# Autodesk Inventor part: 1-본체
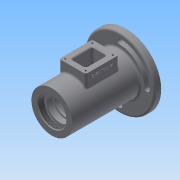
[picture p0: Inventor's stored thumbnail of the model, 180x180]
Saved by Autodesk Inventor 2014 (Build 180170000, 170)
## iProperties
Created: 2017-05
Part Number: 1-본체
Material: Generic
Document SubType Name: Modeling
Designer: user
Density: 1 g/cm^3
Appearance: Default
Author: user
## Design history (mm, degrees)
sketch "Sketch1"
  geometry: L1 (0, 0)-(115, 0); L2 (0, 0)-(0, 31); L3 (0, 31)-(102, 31); L4 (102, 31)-(102, 53); L5 (102, 53)-(112, 53); L6 (112, 53)-(112, 31); L7 (112, 31)-(115, 31); L8 (115, 31)-(115, 0)
  constraints: 16 end point, 4 parallel, 2 perpendicular, 1 collinear, 1 horizontal
  dimensions: "d0" = 62 diameter of L3 L1; "d1" = 106 diameter of L5 L1; "d2" = 62 diameter of L7 L1; "d3" = 10 distance of L4.end L5.end; "d4" = 3 distance from line of L5.end L8; "d5" = 115 distance between parallel lines of L2 L8
revolve "Revolution1" sketch "Sketch1" stored, may be unused: angle "d6" = 90 deg
sketch "Sketch4"
  geometry: L1 (0, 0)-(115, 0); L2 (115, -31)-(115, 31) reference; L3 (0, 0)-(0, 21); L4 (0, 21)-(9, 21); L5 (0, -31)-(0, 31) reference; L6 (9, 21)-(9, 24); L7 (0, 31)-(102, 31) reference; L8 (9, 24)-(12, 24); L9 (12, 24)-(12, 20); L10 (12, 20)-(21, 20); L11 (21, 20)-(21, 17.5); L12 (21, 17.5)-(24.25, 17.5); L13 (24.25, 17.5)-(24.25, 18.5); L14 (24.25, 18.5)-(26, 18.5); L15 (26, 18.5)-(26, 17.5); L16 (26, 17.5)-(37, 17.5); L17 (37, 17.5)-(37, 26); L18 (37, 26)-(75, 26); L19 (75, 26)-(75, 17.5); L20 (75, 17.5)-(86, 17.5); L21 (86, 17.5)-(86, 16.5); L22 (86, 16.5)-(91, 16.5); L23 (91, 16.5)-(91, 10); L24 (91, 10)-(93.7, 10); L25 (93.7, 10)-(93.7, 12.5); L26 (93.7, 12.5)-(101, 12.5); L27 (101, 12.5)-(101, 16); L28 (101, 16)-(115, 22); L29 (115, 0)-(115, 22)
  constraints: 52 end point, 12 parallel, 11 perpendicular, 1 collinear, 1 midpoint, 1 point on line, 1 vertical
  dimensions: "d10" = 42 diameter of L4 L1; "d11" = 48 diameter of L8 L1; "d12" = 40 diameter of L10 L1; "d13" = 3 distance of L6.end L8.end; "d14" = 12 distance between parallel lines of L9 L5; "d15" = 21 distance between parallel lines of L5 L11; "d16" = 1.75 distance of L13.end L14.end; "d17" = 37 diameter of L14 L1; "d18" = 35 diameter of L12 L1; "d19" = 26 distance from line of L5 L14.end; "d20" = 11 distance of L15.end L16.end; "d21" = 35 diameter of L16 L1; "d22" = 52 diameter of L18 L1; "d29" = 38 distance of L17.end L18.end; "d33" = 35 diameter of L20 L1; "d34" = 11 distance of L19.end L20.end; "d35" = 32 diameter of L27.end L1; "d36" = 44 diameter of L28.end L1; "d37" = 14 distance from line of L2 L27.end; "d38" = 25 diameter of L26 L1; "d39" = 20 diameter of L24 L1; "d40" = 7.3 distance between parallel lines of L25 L27; "d41" = 2.7 distance of L23.end L24.end; "d42" = 33 diameter of L22 L1
revolve "Revolution2" sketch "Sketch4" stored, may be unused: angle "d43" = 90 deg
workplane "Work Plane2"
sketch "Sketch5"
  geometry: L1 (-81, 20)-(-31, 20); L2 (-31, 20)-(-31, -20); L3 (-31, -20)-(-81, -20); L4 (-81, -20)-(-81, 20); L5 (0, 31)-(0, -31) reference; 1 further point
  constraints: 8 end point, 2 parallel, 1 horizontal, 1 perpendicular
  dimensions: "d46" = 50 distance of L1.start L1.end; "d47" = 20 vertical distance of point (0, 0) L1.end; "d48" = 40 distance of L1.end L2.end; "d49" = 31 distance between parallel lines of L5 L2
extrude "Extrusion1" join sketch "Sketch5" stored distance "d50" = 10; taper "d51" = 0 deg
sketch "Sketch6"
  geometry: L1 (-72, 11)-(-40, 11); L2 (-40, 11)-(-40, -11); L3 (-40, -11)-(-72, -11); L4 (-72, -11)-(-72, 11); L5 (0, 31)-(0, -31) reference; 1 further point
  constraints: 8 end point, 2 parallel, 1 horizontal, 1 perpendicular
  dimensions: "d52" = 22 distance of L1.end L2.end; "d53" = 11 distance from line of point (0, 0) L1; "d54" = 32 distance of L1.start L1.end; "d55" = 40 distance between parallel lines of L5 L2
extrude "Extrusion2" cut sketch "Sketch6" stored distance "d56" = 10; taper "d57" = 0 deg
sketch "Sketch7"
  geometry: L1 (0, 31)-(0, -31) reference; 2 further points
  dimensions: "d58" = 15.5 vertical distance of point (0, 0) point (-35.5, 15.5); "d59" = 35.5 distance from line of L1 point (-35.5, 15.5)
hole "Hole1" sketch "Sketch7" at (-35.5, 15.5) diameter "d60" = 2.459; stored, may be unused: countersink angle "d64" = 90 deg, drill point angle "d66" = 118 deg; dims "d61" = 6, "d62" = 4, "d63" = 2, "d65" = 8
pattern_linear "Rectangular Pattern1" dims "d69" = 31, "d72" = 41
sketch "Sketch8"
  geometry: L1 (0, 0)-(45.5, 0); L2 (44, 20)-(44, -20) reference; L3 (0, 0)-(0, 45.5); L4 (0, 0)-(-45.5, 0); L5 (0, 0)-(0, -45.5); C1 r 31 at (0, 0) reference; C2 r 10 at (0, 0) reference; A1 r 4 centre (0, 41.5) between (0, 45.5) and (0, 37.5); A2 r 4 centre (41.5, 0) between (37.5, 0) and (45.5, 0); A3 r 4 centre (0, -41.5) between (0, -45.5) and (0, -37.5); A4 r 4 centre (-41.5, 0) between (-37.5, 0) and (-45.5, 0); A5 r 37.5 centre (0, 0) between (37.5, 0) and (0, 37.5); A6 r 37.5 centre (0, 0) between (-37.5, 0) and (0, -37.5); A7 r 45.5 centre (0, 0) between (45.5, 0) and (0, 45.5); A8 r 45.5 centre (0, 0) between (-45.5, 0) and (0, -45.5)
  constraints: 16 point on circle, 8 centre point, 8 end point, 4 point on line, 3 perpendicular, 2 coincident, 2 concentric, 1 parallel
  dimensions: "d75" = 4 radius of A1; "d76" = 4 radius of A2; "d77" = 4 radius of A3; "d78" = 4 radius of A4; "d81" = 45.5 radius of A7; "d82" = 37.5 radius of A5
extrude "Extrusion3" cut sketch "Sketch8" distance "d79" = 20; taper "d80" = 0 deg
thread "Thread1" dims "d83" = 10, "d84" = 0
sketch "Sketch9"
  geometry: L1 (0, 0)-(50, 0) reference; L2 (81, 75)-(81, 13) reference; 2 further points
  constraints: 1 other
  dimensions: "d85" = 56 distance from line of L2 point (25, 8); "d86" = 8 distance from line of L1 point (25, 8)
emboss "Emboss1" sketch "Sketch9" dims "d0" = 62, "d1" = 106, "d2" = 62, "d3" = 10, "d4" = 3, "d5" = 115, "d87" = 0.5, "d88" = 0
chamfer "Chamfer1" distance "d89" = 1; stored, may be unused: second distance "d90" = 2, angle "d91" = 45 deg
chamfer "Chamfer2" distance "d92" = 0.7; stored, may be unused: second distance "d93" = 2, angle "d94" = 30 deg
fillet "Fillet1" dims "d95" = 3, "d96" = 0.3
chamfer "Chamfer3" distance "d97" = 1; stored, may be unused: second distance "d98" = 2, angle "d99" = 30 deg
fillet "Fillet2" dims "d100" = 3, "d101" = 0.3
body "Solid1"
other parameters: "d44" = 44, "d73" = 91, "d74" = 75
